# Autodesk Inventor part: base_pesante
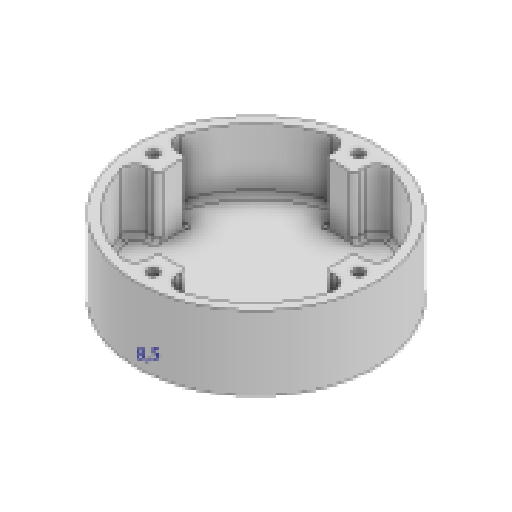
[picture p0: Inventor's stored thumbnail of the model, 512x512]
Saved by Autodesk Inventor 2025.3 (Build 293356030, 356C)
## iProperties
Created: 2025-11
Part Number: base_pesante
Material: Generico
Document SubType Name: Modeling
Designer: R5800u
Density: 1 g/cm^3
Appearance: Default
Author: R5800u
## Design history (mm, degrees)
sketch "Schizzo1"
  geometry: C1 r 50 at (0, 0); 1 further point
  constraints: 1 centre point, 1 coincident
  dimensions: "d0" = 100 diameter of C1
extrude "Estrusione1" new body sketch "Schizzo1" distance "d1" = 5; taper "d2" = 0 deg
sketch "Schizzo2"
  geometry: L1 (0, 0)-(0, 50); L2 (-6, 35)-(6, 35); L3 (6, 35)-(6, 45.607); L4 (5, 49.749)-(5, 50); L5 (-6, 35)-(-6, 45.607); L6 (-5, 49.749)-(-5, 50); L7 (-35, -6)-(-35, 6); L8 (-35, 6)-(-45.607, 6); L9 (-35, -6)-(-45.607, -6); L10 (6, -35)-(-6, -35); L11 (-6, -35)-(-6, -45.607); L12 (6, -35)-(6, -45.607); L13 (35, 6)-(35, -6); L14 (35, -6)-(45.607, -6); L15 (35, 6)-(45.607, 6); C1 r 2.009 at (0, -40) reference; C2 r 2.009 at (-40, 0) reference; C3 r 2.009 at (0, 40) reference; C4 r 2.009 at (40, 0) reference; C5 r 35.25 at (0, 0); A1 r 50 centre (0, 0) between (0, 50) and (5, 49.749) reference; A2 r 46 centre (0, 0) between (6, 45.607) and (-6, 45.607); 26 further points
  constraints: 30 end point, 5 point on circle, 4 parallel, 2 centre point, 2 perpendicular, 1 coincident, 1 vertical, 33 other
  dimensions: "d3" = 4 radial gap between concentric circles of A1 A2; "d6" = 35 distance from line of point (0, 0) L2; "d9" = 360 deg dimension on point (0, 0) C3.centre (derived); "d11" = 70.5 diameter of C5; "d23" = 6 distance between parallel lines of L1 L5; "d24" = 6 distance between parallel lines of L1 L3
extrude "Estrusione2" join sketch "Schizzo2" distance "d12" = 26; taper "d13" = 0 deg
fillet "Raccordo2" dims "d15" = 5
sketch "Schizzo3"
  geometry: C1 r 2.009 at (-43, 0); 3 further points
  constraints: 1 centre point, 1 coincident
hole "Foro1" sketch "Schizzo3" at (-43, 0) diameter "d16" = 4.5; stored, may be unused: countersink angle "d20" = 90 deg, drill point angle "d22" = 118 deg; dims "d17" = 6, "d18" = 10, "d19" = 5.7, "d21" = 8
fillet "Raccordo3" dims "d25" = 2
pattern_circular "Serie circolare1" dims angle "d27" = 360 deg
node "Piano di lavoro1"
sketch "Schizzo4"
  geometry: L1 (22.622, 44.154)-(22.622, -44.163); L2 (22.622, -44.163)-(12.233, -44.163); L3 (12.233, -44.163)-(12.233, 44.154); L4 (12.233, 44.154)-(22.622, 44.154); 1 further point
  constraints: 2 other
feature "Sbalzo1" sketch "Schizzo4" dims "d3" = 4, "d6" = 35, "d23" = 6, "d24" = 6, "d29" = 0.3, "d30" = 0
pattern_circular "Serie circolare2" dims angle "d32" = 360 deg
sketch "Schizzo5"
  geometry: C1 r 2.25 at (-43, 0) reference; C2 r 50 at (0, 0) reference; 1 further point
extrude "Estrusione3" join sketch "Schizzo5" distance "d34" = 20; taper "d35" = 0 deg
fillet "Raccordo4" dims "d36" = 2
pattern_circular "Serie circolare3" dims angle "d39" = 360 deg
sketch "Schizzo6" dims "d41" = 8.5
  geometry: L1 (4.25, 43)-(2.125, 39.319); L2 (2.125, 39.319)-(-2.125, 39.319); L3 (-2.125, 39.319)-(-4.25, 43); L4 (-4.25, 43)-(-2.125, 46.681); L5 (-2.125, 46.681)-(2.125, 46.681); L6 (2.125, 46.681)-(4.25, 43); C1 r 2.25 at (0, 43) reference; 3 further points
  constraints: 12 end point, 2 coincident, 1 horizontal alignment, 15 other
extrude "Estrusione4" cut sketch "Schizzo6" distance "d42" = 10; taper "d43" = 0 deg
pattern_circular "Serie circolare4" dims angle "d45" = 360 deg
node "Solido1"
node "Linea chiusa proiettata1"
node "Riferimento1"
node "Riferimento2"
node "Riferimento3"
node "Riferimento4"
node "Schizzo - Serie circolare1" dims "d9" = 360 deg (derived)
node "Linea chiusa proiettata2"
other parameters: "d4" = 5, "d5" = 5
